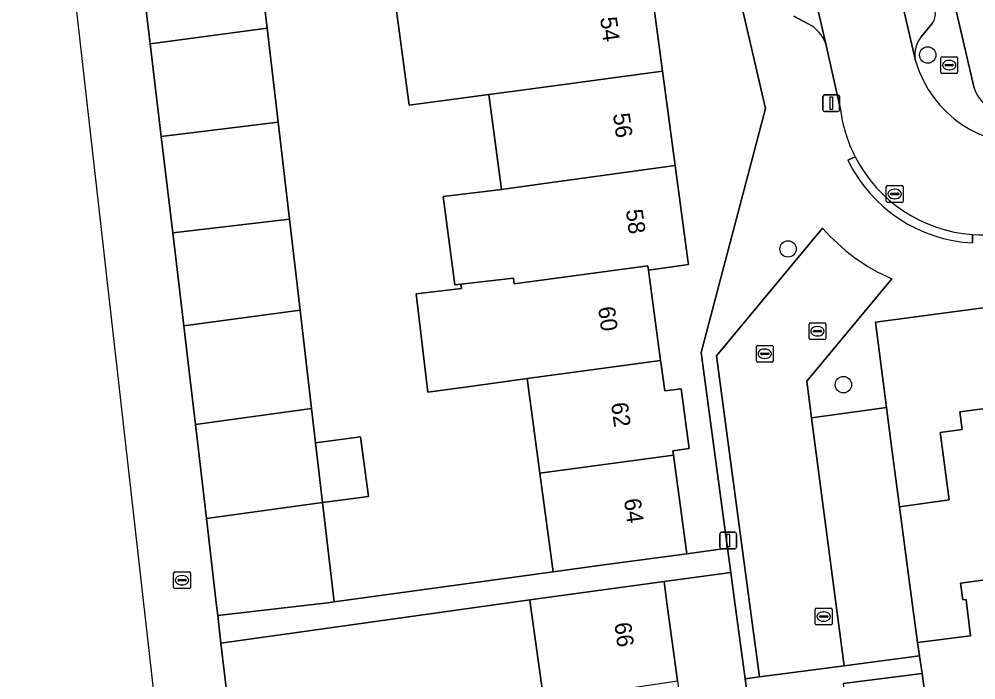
# Model space of a CAD drawing. Extents: x 163426 to 164192, y 380329 to 381641.
# Drawn here: x 163529.1 to 163586.2, y 381245.4 to 381284.8 of the extents above; entities that cross this region are included whole.
import ezdxf

# ---------------------------------------------------------------- set-up
doc = ezdxf.new("R2010")
doc.units = 0
for name, color, linetype in [('IMGEO_Boom', 7, 'Continuous'), ('IMGEO_Brandkraan', 7, 'Continuous'), ('IMGEO_Erf', 7, 'Continuous'), ('IMGEO_Groenvoorziening', 7, 'Continuous'), ('IMGEO_Kolk', 7, 'Continuous'), ('IMGEO_Lichtmast', 7, 'Continuous'), ('IMGEO_Pand', 7, 'Continuous'), ('IMGEO_Pand_nummerreeks', 7, 'Continuous'), ('IMGEO_Parkeervlak_open', 7, 'Continuous'), ('IMGEO_Rijbaan_lokaal_open', 7, 'Continuous'), ('IMGEO_Rioolput', 7, 'Continuous'), ('IMGEO_Voetpad_open', 7, 'Continuous')]:
    doc.layers.add(name, color=color, linetype=linetype)

msp = doc.modelspace()

# ---------------------------------------------------------------- linework, layer by layer
at = {"layer": 'IMGEO_Boom'}
for centre in [(163583.337, 381282.697), (163574.997, 381271.122), (163578.303, 381263.017)]:
    msp.add_circle(centre, 0.489, dxfattribs=at)
at = {"layer": 'IMGEO_Brandkraan'}
for p, q in [((163584.124, 381281.669), (163584.124, 381282.521)), ((163584.199, 381282.595), (163585.051, 381282.595)), ((163584.612, 381282.375), (163584.637, 381282.375)), ((163585.125, 381282.521), (163585.125, 381281.669)), ((163584.383, 381282.089), (163584.383, 381282.101)), ((163584.821, 381282.052), (163584.423, 381282.052)), ((163584.426, 381282.138), (163584.824, 381282.138)), ((163584.635, 381281.815), (163584.61, 381281.815)), ((163584.867, 381282.101), (163584.867, 381282.089)), ((163585.051, 381281.595), (163584.199, 381281.595))]:
    msp.add_line(p, q, dxfattribs=at)
for points in [[(163584.124, 381281.669), (163584.124, 381282.521)], [(163584.199, 381282.595), (163585.051, 381282.595)], [(163585.125, 381282.521), (163585.125, 381281.669)], [(163585.051, 381281.595), (163584.199, 381281.595)]]:
    msp.add_lwpolyline(points, dxfattribs=at)
for centre, radius, start, end in [((163584.201, 381282.519), 0.0765, 91.552, 178.448), ((163584.201, 381282.519), 0.0765, 91.552, 178.448), ((163585.049, 381282.519), 0.0765, 1.552, 88.448), ((163585.049, 381282.519), 0.0765, 1.552, 88.448), ((163584.201, 381281.671), 0.0765, 181.552, 268.448), ((163584.201, 381281.671), 0.0765, 181.552, 268.448), ((163584.423, 381282.098), 0.0403, 85.8775, 175.7526), ((163584.42, 381282.088), 0.0366, 178.938, 274.7102), ((163584.824, 381282.095), 0.043, 264.8664, 352.4533), ((163584.828, 381282.1), 0.0386, 1.7309, 96.639), ((163585.049, 381281.671), 0.0765, 271.552, 358.448), ((163585.049, 381281.671), 0.0765, 271.552, 358.448)]:
    msp.add_arc(centre, radius, start, end, dxfattribs=at)
for centre, major_axis, ratio, start_param, end_param in [((163584.611, 381282.095), (-0.387, 0.002), 0.722429, 4.712389, 7.853982), ((163584.636, 381282.095), (-0.39, 0.002), 0.717154, 1.570796, 4.712389)]:
    msp.add_ellipse(centre, major_axis=major_axis, ratio=ratio, start_param=start_param, end_param=end_param, dxfattribs=at)
at = {"layer": 'IMGEO_Erf'}
for points in [[(163574.547, 381330.467), (163586.109, 381280.708)], [(163542.985, 381291.97), (163543.883, 381284.302), (163544.541, 381278.686), (163545.218, 381272.903), (163545.855, 381267.467), (163546.543, 381261.594), (163546.784, 381259.54), (163549.464, 381259.905), (163549.947, 381256.349), (163547.201, 381255.976), (163547.895, 381250.048), (163560.965, 381251.85), (163560.172, 381257.74), (163559.412, 381263.379), (163556.289, 381262.953), (163553.483, 381262.57), (163552.795, 381268.443), (163555.492, 381268.759), (163555.462, 381269.015), (163555.107, 381268.973), (163554.4, 381274.255), (163557.892, 381274.664), (163557.128, 381280.333), (163552.38, 381279.696), (163551.624, 381285.34)], [(163641.538, 381274.912), (163580.21, 381266.748), (163580.871, 381261.661), (163581.157, 381259.489), (163581.653, 381255.731), (163584.627, 381256.137), (163584.116, 381259.892), (163584.078, 381260.169), (163585.389, 381260.343), (163585.249, 381261.394), (163589.066, 381261.9)], [(163590.691, 381251.896), (163585.302, 381251.179), (163585.434, 381250.168), (163585.629, 381250.194), (163585.653, 381250), (163585.901, 381248.02), (163582.725, 381247.624), (163582.844, 381246.832), (163583.002, 381245.775), (163585.892, 381224.307), (163586.031, 381223.272), (163586.138, 381222.481), (163589.314, 381222.876)], [(163560.416, 381244.138), (163559.597, 381250), (163559.574, 381250.17), (163541.132, 381247.593), (163541.553, 381243.922)]]:
    msp.add_lwpolyline(points, dxfattribs=at)
for points in [[(163573.656, 381279.496), (163569.929, 381295.551), (163565.729, 381294.993), (163566.747, 381287.4), (163567.506, 381281.74), (163568.263, 381276.091), (163569.02, 381270.441), (163569.055, 381270.182), (163566.66, 381269.852), (163567.389, 381264.458), (163567.42, 381264.228), (163567.634, 381262.642), (163568.614, 381262.775), (163569.09, 381259.206), (163568.116, 381259.074), (163568.152, 381258.809), (163568.947, 381252.927), (163571.382, 381253.255), (163569.808, 381264.93)], [(163573.72, 381235.921), (163572.433, 381245.465), (163571.821, 381250), (163571.578, 381251.805), (163567.596, 381251.268), (163567.767, 381250), (163568.395, 381245.333), (163569.154, 381239.694), (163569.917, 381234.025), (163570.676, 381228.385), (163571.437, 381222.736), (163572.237, 381216.791), (163576.227, 381217.329)]]:
    msp.add_lwpolyline(points, close=True, dxfattribs=at)
msp.add_arc((163588.223, 381281.419), 2.23, 198.5916, 280.6222, dxfattribs=at)
at = {"layer": 'IMGEO_Groenvoorziening'}
msp.add_lwpolyline([(163583.002, 381245.775), (163578.294, 381245.185), (163579.055, 381239.257), (163581.052, 381223.686), (163585.892, 381224.307)], close=True, dxfattribs=at)
at = {"layer": 'IMGEO_Kolk'}
for p, q in [((163576.251, 381265.78), (163576.251, 381266.632)), ((163576.326, 381266.706), (163577.178, 381266.706)), ((163576.553, 381266.249), (163576.951, 381266.249)), ((163576.739, 381266.486), (163576.764, 381266.486)), ((163577.252, 381266.632), (163577.252, 381265.78)), ((163577.178, 381265.706), (163576.326, 381265.706)), ((163576.51, 381266.2), (163576.51, 381266.212)), ((163576.948, 381266.163), (163576.55, 381266.163)), ((163576.762, 381265.926), (163576.737, 381265.926)), ((163576.994, 381266.212), (163576.994, 381266.2)), ((163538.307, 381250.919), (163538.307, 381251.771)), ((163538.382, 381251.845), (163539.234, 381251.845)), ((163538.609, 381251.388), (163539.007, 381251.388)), ((163538.795, 381251.625), (163538.82, 381251.625)), ((163539.308, 381251.771), (163539.308, 381250.919)), ((163539.234, 381250.845), (163538.382, 381250.845)), ((163538.566, 381251.339), (163538.566, 381251.351)), ((163539.004, 381251.302), (163538.606, 381251.302)), ((163538.818, 381251.065), (163538.793, 381251.065)), ((163539.05, 381251.351), (163539.05, 381251.339)), ((163576.698, 381249.676), (163577.55, 381249.676)), ((163576.623, 381248.75), (163576.623, 381249.602)), ((163576.882, 381249.17), (163576.882, 381249.182)), ((163577.32, 381249.133), (163576.922, 381249.133)), ((163576.925, 381249.219), (163577.323, 381249.219)), ((163577.111, 381249.456), (163577.136, 381249.456)), ((163577.366, 381249.182), (163577.366, 381249.17)), ((163577.624, 381249.602), (163577.624, 381248.75)), ((163577.55, 381248.676), (163576.698, 381248.676)), ((163577.134, 381248.896), (163577.109, 381248.896))]:
    msp.add_line(p, q, dxfattribs=at)
for points in [[(163576.251, 381265.78), (163576.251, 381266.632)], [(163576.326, 381266.706), (163577.178, 381266.706)], [(163577.252, 381266.632), (163577.252, 381265.78)], [(163577.178, 381265.706), (163576.326, 381265.706)], [(163538.307, 381250.919), (163538.307, 381251.771)], [(163538.382, 381251.845), (163539.234, 381251.845)], [(163539.308, 381251.771), (163539.308, 381250.919)], [(163539.234, 381250.845), (163538.382, 381250.845)], [(163576.698, 381249.676), (163577.55, 381249.676)], [(163576.623, 381248.75), (163576.623, 381249.602)], [(163577.624, 381249.602), (163577.624, 381248.75)], [(163577.55, 381248.676), (163576.698, 381248.676)]]:
    msp.add_lwpolyline(points, dxfattribs=at)
for centre, radius, start, end in [((163576.328, 381266.63), 0.0765, 91.552, 178.448), ((163576.328, 381266.63), 0.0765, 91.552, 178.448), ((163576.55, 381266.209), 0.0403, 85.8775, 175.7526), ((163576.955, 381266.211), 0.0386, 1.7309, 96.639), ((163577.176, 381266.63), 0.0765, 1.552, 88.448), ((163577.176, 381266.63), 0.0765, 1.552, 88.448), ((163576.328, 381265.782), 0.0765, 181.552, 268.448), ((163576.328, 381265.782), 0.0765, 181.552, 268.448), ((163576.547, 381266.199), 0.0366, 178.938, 274.7102), ((163576.951, 381266.206), 0.043, 264.8664, 352.4533), ((163577.176, 381265.782), 0.0765, 271.552, 358.448), ((163577.176, 381265.782), 0.0765, 271.552, 358.448), ((163538.384, 381251.769), 0.0765, 91.552, 178.448), ((163538.384, 381251.769), 0.0765, 91.552, 178.448), ((163538.606, 381251.348), 0.0403, 85.8775, 175.7526), ((163539.011, 381251.35), 0.0386, 1.7309, 96.639), ((163539.232, 381251.769), 0.0765, 1.552, 88.448), ((163539.232, 381251.769), 0.0765, 1.552, 88.448), ((163538.384, 381250.921), 0.0765, 181.552, 268.448), ((163538.384, 381250.921), 0.0765, 181.552, 268.448), ((163538.603, 381251.338), 0.0366, 178.938, 274.7102), ((163539.007, 381251.345), 0.043, 264.8664, 352.4533), ((163539.232, 381250.921), 0.0765, 271.552, 358.448), ((163539.232, 381250.921), 0.0765, 271.552, 358.448), ((163576.7, 381249.6), 0.0765, 91.552, 178.448), ((163576.7, 381249.6), 0.0765, 91.552, 178.448), ((163577.548, 381249.6), 0.0765, 1.552, 88.448), ((163577.548, 381249.6), 0.0765, 1.552, 88.448), ((163576.922, 381249.179), 0.0403, 85.8775, 175.7526), ((163576.919, 381249.169), 0.0366, 178.938, 274.7102), ((163577.323, 381249.176), 0.043, 264.8664, 352.4533), ((163577.327, 381249.181), 0.0386, 1.7309, 96.639), ((163576.7, 381248.752), 0.0765, 181.552, 268.448), ((163576.7, 381248.752), 0.0765, 181.552, 268.448), ((163577.548, 381248.752), 0.0765, 271.552, 358.448), ((163577.548, 381248.752), 0.0765, 271.552, 358.448)]:
    msp.add_arc(centre, radius, start, end, dxfattribs=at)
for centre, major_axis, ratio, start_param, end_param in [((163576.738, 381266.206), (-0.387, 0.002), 0.722429, 4.712389, 7.853982), ((163576.763, 381266.206), (-0.39, 0.002), 0.717154, 1.570796, 4.712389), ((163538.794, 381251.345), (-0.387, 0.002), 0.722429, 4.712389, 7.853982), ((163538.819, 381251.345), (-0.39, 0.002), 0.717154, 1.570796, 4.712389), ((163577.11, 381249.176), (-0.387, 0.002), 0.722429, 4.712389, 7.853982), ((163577.135, 381249.176), (-0.39, 0.002), 0.717154, 1.570796, 4.712389)]:
    msp.add_ellipse(centre, major_axis=major_axis, ratio=ratio, start_param=start_param, end_param=end_param, dxfattribs=at)
at = {"layer": 'IMGEO_Lichtmast'}
for p, q in [((163577.083, 381279.417), (163577.083, 381280.217)), ((163577.083, 381280.217), (163577.083, 381279.417)), ((163577.183, 381280.317), (163577.973, 381280.317)), ((163577.973, 381280.317), (163577.183, 381280.317)), ((163578.073, 381280.217), (163578.073, 381279.417)), ((163578.073, 381279.417), (163578.073, 381280.217)), ((163577.973, 381279.317), (163577.183, 381279.317)), ((163577.183, 381279.317), (163577.973, 381279.317)), ((163570.926, 381253.315), (163570.926, 381254.115)), ((163570.926, 381254.115), (163570.926, 381253.315)), ((163571.026, 381254.215), (163571.816, 381254.215)), ((163571.816, 381254.215), (163571.026, 381254.215)), ((163571.916, 381254.115), (163571.916, 381253.315)), ((163571.916, 381253.315), (163571.916, 381254.115)), ((163571.816, 381253.215), (163571.026, 381253.215)), ((163571.026, 381253.215), (163571.816, 381253.215))]:
    msp.add_line(p, q, dxfattribs=at)
for points in [[(163577.503, 381280.192), (163577.653, 381280.192), (163577.653, 381279.442), (163577.503, 381279.442), (163577.503, 381280.192)], [(163571.346, 381254.09), (163571.496, 381254.09), (163571.496, 381253.34), (163571.346, 381253.34), (163571.346, 381254.09)]]:
    msp.add_lwpolyline(points, dxfattribs=at)
for centre, start, end in [((163577.183, 381280.217), 90, 180), ((163577.183, 381280.217), 90, 180), ((163577.973, 381280.217), 0, 90), ((163577.973, 381280.217), 360, 90), ((163577.183, 381279.417), 180, 270), ((163577.183, 381279.417), 180, 270), ((163577.973, 381279.417), 270, 0), ((163577.973, 381279.417), 270, 0), ((163571.026, 381254.115), 90, 180), ((163571.026, 381254.115), 90, 180), ((163571.816, 381254.115), 0, 90), ((163571.816, 381254.115), 360, 90), ((163571.026, 381253.315), 180, 270), ((163571.026, 381253.315), 180, 270), ((163571.816, 381253.315), 270, 0), ((163571.816, 381253.315), 270, 0)]:
    msp.add_arc(centre, 0.1, start, end, dxfattribs=at)
at = {"layer": 'IMGEO_Pand'}
for points in [[(163543.883, 381284.302), (163542.985, 381291.97), (163535.974, 381291.167), (163536.906, 381283.368)], [(163566.747, 381287.4), (163558.772, 381286.297), (163556.368, 381285.975), (163551.624, 381285.34), (163552.38, 381279.696), (163557.128, 381280.333), (163559.532, 381280.648), (163567.506, 381281.74)], [(163537.566, 381277.841), (163543.566, 381278.558), (163544.541, 381278.686), (163543.883, 381284.302), (163536.906, 381283.368)], [(163557.128, 381280.333), (163557.892, 381274.664), (163560.292, 381274.998), (163568.263, 381276.091), (163567.506, 381281.74), (163559.532, 381280.648)], [(163538.254, 381272.075), (163545.218, 381272.903), (163544.541, 381278.686), (163543.566, 381278.558), (163537.566, 381277.841)], [(163568.263, 381276.091), (163560.292, 381274.998), (163557.892, 381274.664), (163554.4, 381274.255), (163555.107, 381268.973), (163555.462, 381269.015), (163558.603, 381269.383), (163558.651, 381269.028), (163566.624, 381270.115), (163566.66, 381269.852), (163569.055, 381270.182), (163569.02, 381270.441)], [(163545.855, 381267.467), (163545.218, 381272.903), (163538.254, 381272.075), (163538.916, 381266.538)], [(163566.66, 381269.852), (163566.624, 381270.115), (163558.651, 381269.028), (163558.603, 381269.383), (163555.462, 381269.015), (163555.492, 381268.759), (163552.795, 381268.443), (163553.483, 381262.57), (163556.289, 381262.953), (163559.412, 381263.379), (163567.389, 381264.458)], [(163545.855, 381267.467), (163538.916, 381266.538), (163539.341, 381262.978), (163539.615, 381260.632), (163546.543, 381261.594)], [(163568.152, 381258.809), (163568.116, 381259.074), (163569.09, 381259.206), (163568.614, 381262.775), (163567.634, 381262.642), (163567.42, 381264.228), (163567.389, 381264.458), (163559.412, 381263.379), (163560.172, 381257.74)], [(163589.488, 381260.886), (163589.206, 381260.849), (163589.066, 381261.9), (163585.249, 381261.394), (163585.389, 381260.343), (163584.078, 381260.169), (163584.116, 381259.892), (163584.627, 381256.137), (163581.653, 381255.731), (163582.411, 381250), (163582.725, 381247.624), (163585.901, 381248.02), (163585.653, 381250), (163585.629, 381250.194), (163585.434, 381250.168), (163585.302, 381251.179), (163590.691, 381251.896)], [(163546.784, 381259.54), (163546.543, 381261.594), (163539.615, 381260.632), (163540.268, 381255.034), (163547.201, 381255.976)], [(163546.784, 381259.54), (163547.201, 381255.976), (163549.947, 381256.349), (163549.464, 381259.905)], [(163568.152, 381258.809), (163560.172, 381257.74), (163560.965, 381251.85), (163563.992, 381252.258), (163568.947, 381252.927)], [(163547.201, 381255.976), (163540.268, 381255.034), (163540.855, 381250), (163540.944, 381249.234), (163547.485, 381250), (163547.895, 381250.048)], [(163568.395, 381245.333), (163567.767, 381250), (163567.596, 381251.268), (163562.643, 381250.59), (163559.574, 381250.17), (163559.597, 381250), (163560.416, 381244.138)]]:
    msp.add_lwpolyline(points, close=True, dxfattribs=at)
at = {"layer": 'IMGEO_Parkeervlak_open'}
for points in [[(163571.811, 381328.872), (163577.154, 381305.862), (163577.769, 381303.212), (163582.593, 381282.442)], [(163577.254, 381283.368), (163576.744, 381285.596), (163573.028, 381302.074), (163572.362, 381304.745), (163572.087, 381305.625), (163567.904, 381323.7), (163567.201, 381326.721)], [(163575.348, 381285.014), (163576.207, 381284.549)], [(163582.953, 381283.787), (163583.608, 381284.57)]]:
    msp.add_lwpolyline(points, dxfattribs=at)
msp.add_lwpolyline([(163576.403, 381261.039), (163577.856, 381250), (163578.351, 381246.24), (163582.844, 381246.832), (163582.725, 381247.624), (163582.411, 381250), (163581.653, 381255.731), (163581.157, 381259.489), (163580.871, 381261.661)], close=True, dxfattribs=at)
for centre, radius, start, end in [((163582.878, 381285.122), 0.915, 322.9316, 11.3652), ((163575.205, 381282.606), 2.187, 20.4029, 62.7134), ((163584.205, 381282.731), 1.637, 139.8535, 190.1776)]:
    msp.add_arc(centre, radius, start, end, dxfattribs=at)
at = {"layer": 'IMGEO_Rijbaan_lokaal_open'}
for points in [[(163529.08, 381315.546), (163549.87, 381132.002)], [(163582.628, 381282.289), (163582.593, 381282.442), (163577.769, 381303.212), (163573.028, 381302.074), (163576.744, 381285.596), (163577.254, 381283.368), (163578.129, 381279.443)], [(163541.553, 381243.922), (163541.132, 381247.593), (163540.944, 381249.234), (163540.855, 381250), (163540.268, 381255.034), (163539.615, 381260.632), (163539.341, 381262.978), (163538.916, 381266.538), (163538.254, 381272.075), (163537.566, 381277.841), (163536.906, 381283.368), (163535.974, 381291.167)], [(163577.054, 381272.359), (163570.715, 381264.742), (163572.697, 381250), (163573.292, 381245.577), (163578.351, 381246.24), (163577.856, 381250), (163576.403, 381261.039), (163576.113, 381263.228), (163581.203, 381269.338)]]:
    msp.add_lwpolyline(points, dxfattribs=at)
for centre, radius, start, end in [((163589.222, 381284.262), 6.883, 196.6599, 275.5165), ((163586.56, 381280.506), 8.498, 187.1879, 207.2453), ((163586.613, 381280.503), 8.543, 207.061, 266.02), ((163585.847, 381280.075), 11.698, 221.2689, 246.6123), ((163586.635, 381280.442), 8.485, 265.8447, 286.1372)]:
    msp.add_arc(centre, radius, start, end, dxfattribs=at)
at = {"layer": 'IMGEO_Rioolput'}
for p, q in [((163580.863, 381273.974), (163580.863, 381274.826)), ((163580.938, 381274.9), (163581.79, 381274.9)), ((163581.864, 381274.826), (163581.864, 381273.974)), ((163581.122, 381274.394), (163581.122, 381274.406)), ((163581.56, 381274.357), (163581.162, 381274.357)), ((163581.165, 381274.443), (163581.563, 381274.443)), ((163581.351, 381274.68), (163581.376, 381274.68)), ((163581.606, 381274.406), (163581.606, 381274.394)), ((163581.79, 381273.9), (163580.938, 381273.9)), ((163581.374, 381274.12), (163581.349, 381274.12)), ((163573.103, 381264.439), (163573.103, 381265.291)), ((163573.178, 381265.365), (163574.03, 381265.365)), ((163573.591, 381265.145), (163573.616, 381265.145)), ((163574.104, 381265.291), (163574.104, 381264.439)), ((163573.362, 381264.859), (163573.362, 381264.871)), ((163573.8, 381264.822), (163573.402, 381264.822)), ((163573.405, 381264.908), (163573.803, 381264.908)), ((163573.614, 381264.585), (163573.589, 381264.585)), ((163573.846, 381264.871), (163573.846, 381264.859)), ((163574.03, 381264.365), (163573.178, 381264.365))]:
    msp.add_line(p, q, dxfattribs=at)
for points in [[(163580.863, 381273.974), (163580.863, 381274.826)], [(163580.938, 381274.9), (163581.79, 381274.9)], [(163581.864, 381274.826), (163581.864, 381273.974)], [(163581.79, 381273.9), (163580.938, 381273.9)], [(163573.103, 381264.439), (163573.103, 381265.291)], [(163573.178, 381265.365), (163574.03, 381265.365)], [(163574.104, 381265.291), (163574.104, 381264.439)], [(163574.03, 381264.365), (163573.178, 381264.365)]]:
    msp.add_lwpolyline(points, dxfattribs=at)
for centre, radius, start, end in [((163580.94, 381274.824), 0.0765, 91.552, 178.448), ((163580.94, 381274.824), 0.0765, 91.552, 178.448), ((163581.788, 381274.824), 0.0765, 1.552, 88.448), ((163581.788, 381274.824), 0.0765, 1.552, 88.448), ((163581.162, 381274.403), 0.0403, 85.8775, 175.7526), ((163581.159, 381274.393), 0.0366, 178.938, 274.7102), ((163581.563, 381274.4), 0.043, 264.8664, 352.4533), ((163581.567, 381274.405), 0.0386, 1.7309, 96.639), ((163580.94, 381273.976), 0.0765, 181.552, 268.448), ((163580.94, 381273.976), 0.0765, 181.552, 268.448), ((163581.788, 381273.976), 0.0765, 271.552, 358.448), ((163581.788, 381273.976), 0.0765, 271.552, 358.448), ((163573.18, 381265.289), 0.0765, 91.552, 178.448), ((163573.18, 381265.289), 0.0765, 91.552, 178.448), ((163574.028, 381265.289), 0.0765, 1.552, 88.448), ((163574.028, 381265.289), 0.0765, 1.552, 88.448), ((163573.402, 381264.868), 0.0403, 85.8775, 175.7526), ((163573.399, 381264.858), 0.0366, 178.938, 274.7102), ((163573.803, 381264.865), 0.043, 264.8664, 352.4533), ((163573.807, 381264.87), 0.0386, 1.7309, 96.639), ((163573.18, 381264.441), 0.0765, 181.552, 268.448), ((163573.18, 381264.441), 0.0765, 181.552, 268.448), ((163574.028, 381264.441), 0.0765, 271.552, 358.448), ((163574.028, 381264.441), 0.0765, 271.552, 358.448)]:
    msp.add_arc(centre, radius, start, end, dxfattribs=at)
for centre, major_axis, ratio, start_param, end_param in [((163581.35, 381274.4), (-0.387, 0.002), 0.722429, 4.712389, 7.853982), ((163581.375, 381274.4), (-0.39, 0.002), 0.717154, 1.570796, 4.712389), ((163573.59, 381264.865), (-0.387, 0.002), 0.722429, 4.712389, 7.853982), ((163573.615, 381264.865), (-0.39, 0.002), 0.717154, 1.570796, 4.712389)]:
    msp.add_ellipse(centre, major_axis=major_axis, ratio=ratio, start_param=start_param, end_param=end_param, dxfattribs=at)
at = {"layer": 'IMGEO_Voetpad_open'}
for points in [[(163586.109, 381280.708), (163574.547, 381330.467), (163571.631, 381329.632), (163571.811, 381328.872)], [(163567.201, 381326.721), (163567.036, 381327.472), (163562.879, 381325.922), (163569.602, 381296.96), (163569.929, 381295.551), (163573.656, 381279.496), (163569.808, 381264.93), (163571.382, 381253.255), (163571.578, 381251.805), (163571.821, 381250), (163572.433, 381245.465), (163573.292, 381245.577), (163572.697, 381250), (163570.715, 381264.742), (163577.054, 381272.359)], [(163576.207, 381284.549), (163575.348, 381285.014)], [(163583.608, 381284.57), (163582.953, 381283.787)], [(163578.129, 381279.443), (163577.254, 381283.368)], [(163582.593, 381282.442), (163582.628, 381282.289)], [(163579.005, 381276.616), (163578.574, 381276.415)], [(163578.574, 381276.415), (163579.005, 381276.616)], [(163581.203, 381269.338), (163576.113, 381263.228), (163576.403, 381261.039), (163580.871, 381261.661), (163580.21, 381266.748), (163641.538, 381274.912), (163647.229, 381276.502)], [(163586.011, 381271.481), (163586.02, 381271.98)], [(163586.02, 381271.98), (163586.011, 381271.481)], [(163578.294, 381245.185), (163583.002, 381245.775), (163582.844, 381246.832), (163578.351, 381246.24), (163573.292, 381245.577), (163572.433, 381245.465), (163573.72, 381235.921)]]:
    msp.add_lwpolyline(points, dxfattribs=at)
msp.add_lwpolyline([(163562.643, 381250.59), (163567.596, 381251.268), (163571.578, 381251.805), (163571.382, 381253.255), (163568.947, 381252.927), (163563.992, 381252.258), (163560.965, 381251.85), (163547.895, 381250.048), (163547.485, 381250), (163540.944, 381249.234), (163541.132, 381247.593), (163559.574, 381250.17)], close=True, dxfattribs=at)
for centre, radius, start, end in [((163582.878, 381285.122), 0.915, 322.9316, 11.3652), ((163575.205, 381282.606), 2.187, 20.4029, 62.7134), ((163584.205, 381282.731), 1.637, 139.8535, 190.1776), ((163589.222, 381284.262), 6.883, 196.6599, 275.5165), ((163588.223, 381281.419), 2.23, 198.5916, 280.6222), ((163586.56, 381280.506), 8.498, 187.1879, 207.2453), ((163586.613, 381280.503), 8.543, 207.061, 266.02), ((163586.455, 381280.222), 8.752, 205.7824, 267.0938), ((163586.455, 381280.222), 8.752, 205.7824, 267.0938), ((163585.847, 381280.075), 11.698, 221.2689, 246.6123), ((163586.635, 381280.442), 8.485, 265.8447, 286.1372)]:
    msp.add_arc(centre, radius, start, end, dxfattribs=at)

# ---------------------------------------------------------------- texts
at = {"layer": 'IMGEO_Pand_nummerreeks'}
for s, rotation, p in [('54', 277.6316, (163563.771, 381284.914)), ('56', 277.6342, (163564.54, 381279.174)), ('58', 277.6316, (163565.31, 381273.432)), ('60', 277.6946, (163563.651, 381267.627)), ('62', 277.6955, (163564.425, 381261.904)), ('64', 277.6955, (163565.199, 381256.171)), ('66', 277.6671, (163564.622, 381248.775))]:
    msp.add_text(s, height=1, rotation=rotation, dxfattribs=at).set_placement(p)

doc.saveas('drawing.dxf')
